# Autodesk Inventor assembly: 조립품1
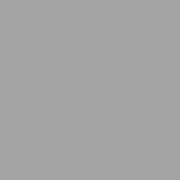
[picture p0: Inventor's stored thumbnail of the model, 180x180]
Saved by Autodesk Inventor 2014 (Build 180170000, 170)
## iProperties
Created: 2015-05
Part Number: 조립품1
Document SubType Name: Assembly
Designer: Administrator
Author: Administrator
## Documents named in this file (1)
- C:\Documents and Settings\Administrator\바탕 화면\450508V1016\조립품1.iam
